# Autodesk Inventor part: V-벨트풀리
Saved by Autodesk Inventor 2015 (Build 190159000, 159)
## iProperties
Created: 2025-08
Part Number: V-벨트풀리
Material: 일반
Document SubType Name: Modeling
Designer: user
Density: 1 g/cm^3
Appearance: 기본값
Author: user
Author: jhkim
Creation Date: 2025-08-05
Sending System: Autodesk Inventor 2026
Preprocessor: ST-DEVELOPER v20.1
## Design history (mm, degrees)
node "V-벨트풀리1"
node "솔리드1"
node "기준1"
